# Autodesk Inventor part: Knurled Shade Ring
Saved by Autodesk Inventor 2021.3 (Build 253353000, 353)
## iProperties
Created: 2022-08
Part Number: Knurled Shade Ring
Material: Generic
Document SubType Name: Modeling
Designer: Administrator
Density: 1 g/cm^3
Appearance: Default
Title: Knurled Shade Ring
Author: Administrator
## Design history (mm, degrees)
feature "Knurled Shade Ring"
body "Solid1"
